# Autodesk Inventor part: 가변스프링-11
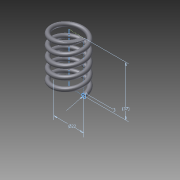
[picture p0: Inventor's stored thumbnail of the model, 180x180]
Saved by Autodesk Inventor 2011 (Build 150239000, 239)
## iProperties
Created: 2015-05
Part Number: 가변스프링-11
Material: 탄소강
Document SubType Name: Modeling
Designer: Administrator
Mass: 19.2243 g
Surface Area: 32.8046 cm^2
Volume: 2.44273 cm^3
Density: 7.87 g/cm^3
Author: Administrator
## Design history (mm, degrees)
sketch "스케치1"
  geometry: L1 (0, 0)-(-11, 0); L2 (-11, 0)-(-11, 25.358); L3 (-11, 25.358)-(0, 25.358); L4 (0, 25.358)-(0, 0); C1 r 1.5 at (-11, 0)
  constraints: 8 end point, 2 parallel, 1 centre point, 1 coincident, 1 horizontal, 1 perpendicular
  dimensions: "d0" = 3 diameter of C1; "d1" = 22 diameter of L2 L4; "d2" = 25.35829 distance of L1.end L2.end (derived)
feature "코일1" sketch "스케치1" pitch "d3" = 10; turns "d5" = 5; dims "d4" = 25.35829 (= d2), "d6" = 0, angle "d7" = 90 deg, angle "d8" = 90 deg, "d9" = 0, "d10" = 0
node "작업 평면1"
sketch "스케치2"
  geometry: L1 (3, 0)-(0, 0) reference; 1 further point
  constraints: 1 horizontal alignment
extrude "돌출1" cut sketch "스케치2" distance "d11" = 10; taper "d12" = 0 deg
node "작업 평면2"
sketch "스케치3"
  geometry: L1 (0, 0)-(3, 0) reference; 1 further point
  constraints: 1 horizontal alignment
extrude "돌출2" cut sketch "스케치3" distance "d13" = 10; taper "d14" = 0 deg
node "솔리드1"
node "절단 모서리 투영1"
node "절단 모서리 투영2"
